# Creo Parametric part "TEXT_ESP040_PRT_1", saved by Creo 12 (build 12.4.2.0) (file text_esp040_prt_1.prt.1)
Units: Custom; MM, KILOGRAM, SECS

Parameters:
  PTC_WM_ITERATION = "0"
  PTC_WM_VERSION = "-.0"
  PTC_WM_LIFECYCLE_STATE = "In Work"
  PTC_WM_LIFECYCLE = "MO_CADDocument"
  PTC_WM_CREATED_BY = "Maximilian Roepper (Z0017RMS: MO)"
  PTC_WM_CREATED_ON = "18-Sep-26 11:36:42 AM"
  PTC_WM_MODIFIED_BY = "Maximilian Roepper (Z0017RMS: MO)"
  PTC_WM_MODIFIED_ON = "18-Sep-26 11:36:46 AM"
  PDMLINKNUMBER = "PDM000071455260"
  PTC_WM_NAME = "text_esp040_prt_1.prt"
  PTC_WM_NUMBER = "PDM000071455260"

Other parameters: WEIGHT, WEIGHT_FACTOR, WEIGHT_ADD, _MASS_TEMP, _DIFF_TEMP, MC_ERRORS, SUPPLIER

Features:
  1. coordinate system
  2. datum plane "PRT_YZ"
  3. datum plane "PRT_XY"
  4. datum plane "PRT_XZ"
  5. coordinate system
  6. datum axis
  7. datum axis
  8. datum axis
  9. coordinate system
  10. imported feature
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
Other named items: PRT, SIEMENS_MO, DRW_VIEW_ORG, PRT_X, PRT_Y, PRT_Z, CS0, ROUGH_GROB

Layers: 00_STD_CSYS-KSYS, 01_STD_PLANES-EBENEN, 02_STD_AXES-ACHSEN, 03_STD_CSYS-KSYS, 24_IMPORT_FEAT-IMPORT_KE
